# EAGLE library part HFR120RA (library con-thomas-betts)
THOMAS&BETTS
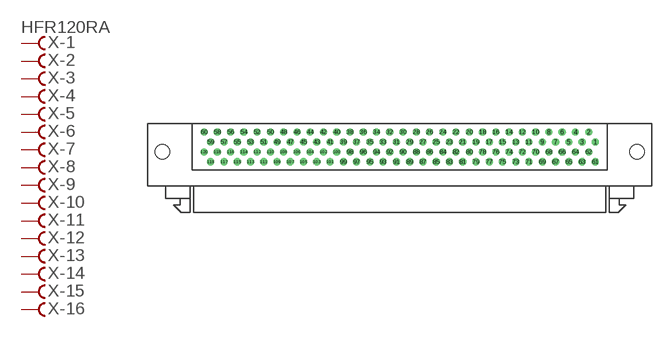
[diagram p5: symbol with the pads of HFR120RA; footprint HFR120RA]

Designator prefix X; gates -1=FV -2=F -3=F -4=F -5=F -6=F -7=F -8=F -9=F -10=F -11=F -12=F -13=F -14=F -15=F -16=F -17=F -18=F -19=F -20=F -21=F -22=F -23=F -24=F -25=F -26=F -27=F -28=F -29=F -30=F -32=F -33=F -34=F -35=F -36=F -37=F -38=F -39=F -40=F -41=F -42=F -43=F -44=F -45=F -46=F -47=F -48=F -49=F -50=F -51=F -52=F -53=F -54=F -55=F -56=F -57=F -58=F -59=F -60=F -62=F -63=F -64=F -65=F -66=F -67=F -68=F -69=F -70=F -71=F -72=F -73=F -74=F -75=F -76=F -77=F -78=F -79=F -80=F -81=F -82=F -83=F -84=F -85=F -86=F -87=F -88=F -89=F -90=F -92=F -93=F -94=F -95=F -96=F -97=F -98=F -99=F -100=F -101=F -102=F -103=F -104=F -105=F -106=F -107=F -108=F -109=F -110=F -111=F -112=F -113=F -114=F -115=F -116=F -117=F -118=F -119=F -120=F -31=F -61=F -91=F

## HFR120RA (OC_FARNELL: unknown; OC_NEWARK: unknown)  [HFR120RA]
1  -1:F  pas
2  -2:F  pas
3  -3:F  pas
4  -4:F  pas
5  -5:F  pas
6  -6:F  pas
7  -7:F  pas
8  -8:F  pas
9  -9:F  pas
10  -10:F  pas
11  -11:F  pas
12  -12:F  pas
13  -13:F  pas
14  -14:F  pas
15  -15:F  pas
16  -16:F  pas
17  -17:F  pas
18  -18:F  pas
19  -19:F  pas
20  -20:F  pas
21  -21:F  pas
22  -22:F  pas
23  -23:F  pas
24  -24:F  pas
25  -25:F  pas
26  -26:F  pas
27  -27:F  pas
28  -28:F  pas
29  -29:F  pas
30  -30:F  pas
31  -31:F  pas
32  -32:F  pas
33  -33:F  pas
34  -34:F  pas
35  -35:F  pas
36  -36:F  pas
37  -37:F  pas
38  -38:F  pas
39  -39:F  pas
40  -40:F  pas
41  -41:F  pas
42  -42:F  pas
43  -43:F  pas
44  -44:F  pas
45  -45:F  pas
46  -46:F  pas
47  -47:F  pas
48  -48:F  pas
49  -49:F  pas
50  -50:F  pas
51  -51:F  pas
52  -52:F  pas
53  -53:F  pas
54  -54:F  pas
55  -55:F  pas
56  -56:F  pas
57  -57:F  pas
58  -58:F  pas
59  -59:F  pas
60  -60:F  pas
61  -61:F  pas
62  -62:F  pas
63  -63:F  pas
64  -64:F  pas
65  -65:F  pas
66  -66:F  pas
67  -67:F  pas
68  -68:F  pas
69  -69:F  pas
70  -70:F  pas
71  -71:F  pas
72  -72:F  pas
73  -73:F  pas
74  -74:F  pas
75  -75:F  pas
76  -76:F  pas
77  -77:F  pas
78  -78:F  pas
79  -79:F  pas
80  -80:F  pas
81  -81:F  pas
82  -82:F  pas
83  -83:F  pas
84  -84:F  pas
85  -85:F  pas
86  -86:F  pas
87  -87:F  pas
88  -88:F  pas
89  -89:F  pas
90  -90:F  pas
91  -91:F  pas
92  -92:F  pas
93  -93:F  pas
94  -94:F  pas
95  -95:F  pas
96  -96:F  pas
97  -97:F  pas
98  -98:F  pas
99  -99:F  pas
100  -100:F  pas
101  -101:F  pas
102  -102:F  pas
103  -103:F  pas
104  -104:F  pas
105  -105:F  pas
106  -106:F  pas
107  -107:F  pas
108  -108:F  pas
109  -109:F  pas
110  -110:F  pas
111  -111:F  pas
112  -112:F  pas
113  -113:F  pas
114  -114:F  pas
115  -115:F  pas
116  -116:F  pas
117  -117:F  pas
118  -118:F  pas
119  -119:F  pas
120  -120:F  pas

## Footprint HFR120RA (pad centres in mm)
THOMAS&BETTS Fine Pitch "D" Connector HFR120RA29xxx
drill 0.864 octagon: 1 37.465,6.98
drill 0.864 round: 2 36.195,8.89; 3 34.925,6.98; 4 33.655,8.89; 5 32.385,6.98; 6 31.115,8.89; 7 29.845,6.98; 8 28.575,8.89; 9 27.305,6.98; 10 26.035,8.89; 11 24.765,6.98; 12 23.495,8.89; 13 22.225,6.98; 14 20.955,8.89; 15 19.685,6.98; 16 18.415,8.89; 17 17.145,6.98; 18 15.875,8.89; 19 14.605,6.98; 20 13.335,8.89; 21 12.065,6.98; 22 10.795,8.89; 23 9.525,6.98; 24 8.255,8.89; 25 6.985,6.98; 26 5.715,8.89; 27 4.445,6.98; 28 3.175,8.89; 29 1.905,6.98; 30 0.635,8.89; 31 -0.635,6.98; 32 -1.905,8.89; 33 -3.175,6.98; 34 -4.445,8.89; 35 -5.715,6.98; 36 -6.985,8.89; 37 -8.255,6.98; 38 -9.525,8.89; 39 -10.795,6.98; 40 -12.065,8.89; 41 -13.335,6.98; 42 -14.605,8.89; 43 -15.875,6.98; 44 -17.145,8.89; 45 -18.415,6.98; 46 -19.685,8.89; 47 -20.955,6.98; 48 -22.225,8.89; 49 -23.495,6.98; 50 -24.765,8.89; 51 -26.035,6.98; 52 -27.305,8.89; 53 -28.575,6.98; 54 -29.845,8.89; 55 -31.115,6.98; 56 -32.385,8.89; 57 -33.655,6.98; 58 -34.925,8.89; 59 -36.195,6.98; 60 -37.465,8.89; 61 37.465,3.16; 62 36.195,5.07; 63 34.925,3.16; 64 33.655,5.07; 65 32.385,3.16; 66 31.115,5.07; 67 29.845,3.16; 68 28.575,5.07; 69 27.305,3.16; 70 26.035,5.07; 71 24.765,3.16; 72 23.495,5.07; 73 22.225,3.16; 74 20.955,5.07; 75 19.685,3.16; 76 18.415,5.07; 77 17.145,3.16; 78 15.875,5.07; 79 14.605,3.16; 80 13.335,5.07; 81 12.065,3.16; 82 10.795,5.07; 83 9.525,3.16; 84 8.255,5.07; 85 6.985,3.16; 86 5.715,5.07; 87 4.445,3.16; 88 3.175,5.07; 89 1.905,3.16; 90 0.635,5.07; 91 -0.635,3.16; 92 -1.905,5.07; 93 -3.175,3.16; 94 -4.445,5.07; 95 -5.715,3.16; 96 -6.985,5.07; 97 -8.255,3.16; 98 -9.525,5.07; 99 -10.795,3.16; 100 -12.065,5.07; 101 -13.335,3.16; 102 -14.605,5.07; 103 -15.875,3.16; 104 -17.145,5.07; 105 -18.415,3.16; 106 -19.685,5.07; 107 -20.955,3.16; 108 -22.225,5.07; 109 -23.495,3.16; 110 -24.765,5.07; 111 -26.035,3.16; 112 -27.305,5.07; 113 -28.575,3.16; 114 -29.845,5.07; 115 -31.115,3.16; 116 -32.385,5.07; 117 -33.655,3.16; 118 -34.925,5.07; 119 -36.195,3.16; 120 -37.465,5.07
hole 2.769 at 45.466,5.07
hole 2.769 at -45.466,5.07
